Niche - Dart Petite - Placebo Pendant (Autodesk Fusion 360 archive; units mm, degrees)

design "Dart - Petite - Modular" references "Modular - Placebo - Bayonet Connector", "Modular - Placedo - Cord Set"
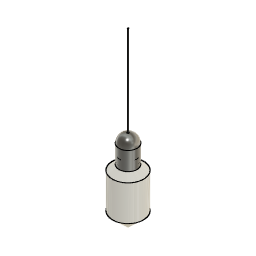
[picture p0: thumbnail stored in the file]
derived_base_feature "Derived Base Feature" bodies "Body1"
sketch "Sketch1" plane through (0, 0, 0) normal (0, 1, 0) x axis (1, 0, 0)
  line L1 (0, 127) -> (0, -444.5)
  line L2 (26.9875, 127) -> (26.9875, -444.5)
  line L3 (-26.9875, 127) -> (-26.9875, -444.5)
  point P4 (26.9875, -444.5)
  point P6 (-26.9875, -444.5)
  point P5 (26.9875, 127)
  point P7 (-26.9875, 127)
  vertical L1
  symmetric L1 P4 P6
  symmetric L1 P5 P7
  dimension "d1" = 26.9875
sketch "Sketch2" plane through (0, 0, 0) normal (0, 1, 0) x axis (1, 0, 0)
  line L1 (26.9371, -176.1141) -> (26.9371, -187.596)
  line L2 (-26.9875, -187.596) -> (-26.9875, -176.1141)
  line L3 (50.7748, -161.2156) -> (26.9371, -176.1141)
  line L4 (-26.9875, -176.1141) -> (-50.8252, -161.2156)
  line L5 (50.7748, -46.9156) -> (50.7748, -161.2156)
  line L6 (-50.8252, -161.2156) -> (-50.8252, -46.9156)
  line L7 (-0.0252, -0.0233) -> (50.7748, -46.9156)
  line L8 (-50.8252, -46.9156) -> (-0.0252, -0.0233)
  line L9 (26.9371, -187.596) -> (-26.9875, -187.596)
  line L10 (-49.5552, -47.4716) -> (0.8614, -0.9332)
  line L11 (-49.5552, -160.5117) -> (-49.5552, -47.4716)
  line L12 (-25.7175, -175.4102) -> (-49.5552, -160.5117)
  line L13 (-25.7175, -187.596) -> (-25.7175, -175.4102)
  line L14 (-0.0252, -0.0233) -> (-0.0252, -187.596)
  point P16 (-0.0252, -187.596)
  point P7 (-50.8252, -161.2156)
  point P9 (-50.8252, -46.9156)
  point P8 (50.7748, -161.2156)
  point P10 (50.7748, -46.9156)
  perpendicular L1 L9
  midpoint L9 P16
  perpendicular L9 L14
  dimension "d2" = -1.27
  dimension "d4" distance L5 L6 = 101.6
  dimension "d5" distance L5 L14 = 50.8
  dimension "d6" distance P7 P9 = 114.3
  dimension "d7" distance P8 P10 = 114.3
revolve "Revolve1" sketch "Sketch2" AlongAngle 360 bodies "Dart Petite Modular"
remove_body "RemoveBody1"
component_from_bodies "Body->Comp"
component_insert "Component Insert1"
component_insert "Component Insert2"
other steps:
base_feature "Base Feature" bodies "Dart Petite Modular"
create_component "CreateComponent1"
remove_body "RemoveBody2"
named bodies: "Body1", "Dart Petite Modular"

design "Modular - Placebo - Bayonet Connector"
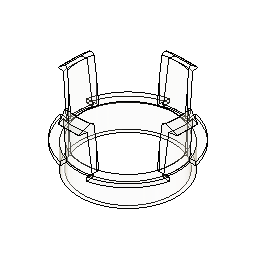
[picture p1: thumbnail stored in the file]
sketch "Sketch1" plane through (0, 0, 0) normal (0, 0, 1) x axis (1, 0, 0)
  circle C1 centre (0, 0) radius 23.241
  point P1 (0, 0)
  point P2 (0, 0)
  coincident P1 P2
  dimension "d1" diameter C1 = 46.482
extrude "Extrude1" new body sketch "Sketch1" along normal blind 11.176
sketch "Sketch2" plane through (0, 0, 11.176) normal (0, 0, 1) x axis (-1, 0, 0)
  line L1 (-23.2795, -6.35) -> (-26.1645, -6.35)
  line L2 (-23.2795, 6.35) -> (-26.1645, 6.35)
  line L3 (26.1645, -6.35) -> (23.2795, -6.35)
  line L4 (26.1645, 6.35) -> (23.2795, 6.35)
  line L5 (6.35, -23.2795) -> (6.35, -26.1645)
  line L6 (-6.35, -23.2795) -> (-6.35, -26.1645)
  line L7 (6.35, 26.1645) -> (6.35, 23.2795)
  line L8 (-6.35, 26.1645) -> (-6.35, 23.2795)
  line L9 (0, -24.13) -> (0, -26.924)
  line L10 (6.35, -23.2795) -> (6.35, -22.3567)
  line L11 (-6.35, -23.2795) -> (-6.35, -22.3567)
  line L12 (23.2795, -6.35) -> (22.3567, -6.35)
  line L13 (23.2795, 6.35) -> (22.3567, 6.35)
  line L14 (-23.2795, 6.35) -> (-22.3567, 6.35)
  line L15 (-23.2795, -6.35) -> (-22.3567, -6.35)
  line L16 (6.35, 22.3567) -> (6.35, 23.2795)
  line L17 (-6.35, 22.3567) -> (-6.35, 23.2795)
  circle C1 centre (0, 0) radius 23.241
  arc A1 centre (0, 0) radius 26.924 clockwise from (-6.35, -26.1645) to (-26.1645, -6.35)
  arc A2 centre (0, 0) radius 26.924 clockwise from (26.1645, -6.35) to (6.35, -26.1645)
  arc A3 centre (0, 0) radius 24.13 clockwise from (23.2795, 6.35) to (23.2795, -6.35)
  arc A4 centre (0, 0) radius 24.13 clockwise from (6.35, -23.2795) to (-6.35, -23.2795)
  arc A5 centre (0, 0) radius 26.924 clockwise from (6.35, 26.1645) to (26.1645, 6.35)
  arc A6 centre (0, 0) radius 26.924 clockwise from (-26.1645, 6.35) to (-6.35, 26.1645)
  arc A7 centre (0, 0) radius 24.13 clockwise from (-6.35, 23.2795) to (6.35, 23.2795)
  arc A8 centre (0, 0) radius 24.13 clockwise from (-23.2795, -6.35) to (-23.2795, 6.35)
  point P2 (0, 0)
  point P4 (0, 0)
  point P12 (-23.2795, -6.35)
  point P13 (-22.3567, -6.35)
  point P14 (-23.2795, 6.35)
  point P15 (-22.3567, 6.35)
  point P16 (22.3567, -6.35)
  point P18 (22.3567, 6.35)
  point P24 (6.35, 23.2795)
  point P28 (6.35, -22.3567)
  point P29 (-6.35, -22.3567)
  point P31 (-6.35, 26.1645)
  point P35 (0, -24.13)
  point P36 (6.35, 22.3567)
  point P37 (-6.35, 22.3567)
  coincident P2 P4
  vertical L9
  concentric A2 A3
  concentric A1 A2
  coincident P12 A3
  coincident C1 P13
  coincident P14 A3
  coincident C1 P15
  coincident C1 P16
  coincident C1 P18
  concentric A2 A5
  coincident P24 L5
  concentric A3 A7
  concentric A4 A7
  coincident C1 P28
  coincident C1 P29
  coincident P31 A5
  concentric A5 A6
  concentric A7 A8
  coincident A4 P35
  horizontal L12
  coincident C1 P36
  parallel L7 L16
  coincident C1 P37
  parallel L8 L17
  dimension "d4" diameter A2 = 53.848
extrude "Extrude2" add sketch "Sketch2" profile of C1 A8 L10 L11 L12 L13 L14 L15 L16 L17 along normal blind 0.762
extrude "Extrude3" add sketch "Sketch2" profile of C1 A6 L7 L8 L4 L3 L10 L11 L12 L13 L14 L15 L16 L17 along normal blind 1.7018
extrude "Extrude4" add sketch "Sketch2" profile of C1 along normal blind 1.7018
work_plane "WorkPlane1" AlongDistance 33.8963
sketch "Sketch3" plane through (0, 0, 33.8963) normal (0, 0, 1) x axis (1, 0, 0)
  line L1 (0, 20.3925) -> (0, 27.5045)
  line L2 (-6.604, 20.3925) -> (-6.604, 27.5045)
  line L3 (6.604, 20.3925) -> (6.604, 27.5045)
  circle C1 centre (0, 0) radius 23.7363
  circle C2 centre (0, 0) radius 27.305
  arc A1 centre (0.0021, 0.2001) radius 23.9364 clockwise from (-6.604, 23.2068) to (6.604, 23.208)
  arc A2 centre (0.0021, 0.2001) radius 21.3964 clockwise from (-6.604, 20.5511) to (6.604, 20.5525)
  point P1 (0, 0)
  point P2 (0, 0)
  point P6 (-6.604, 27.5045)
  point P8 (6.604, 27.5045)
  point P7 (-6.604, 20.3925)
  point P9 (6.604, 20.3925)
  point P11 (-6.604, 23.2068)
  point P12 (6.604, 23.208)
  point P14 (-6.604, 20.5511)
  point P15 (6.604, 20.5525)
  coincident P1 P2
  concentric C1 C2
  vertical L1
  symmetric L1 P6 P8
  symmetric L1 P7 P9
  tangent C1 A1
  coincident L2 P11
  coincident L3 P12
  concentric A1 A2
  coincident L2 P14
  coincident L3 P15
  dimension "d14" diameter C1 = 47.4726
  dimension "d15" diameter C2 = 54.61
  dimension "d16" = 6.604
extrude "Extrude5" new body sketch "Sketch3" profile of C1 L1 L2 L3 A1 A2 against normal blind 21.59
sketch "Sketch4" plane through (0, 0, 33.8963) normal (0, 0, 1) x axis (-1, 0, 0)
  line L1 (6.604, -20.5511) -> (6.604, -23.2068)
  line L2 (-6.604, -23.208) -> (-6.604, -20.5525)
  line L3 (-5.08, -26.67) -> (-6.604, -20.5525)
  line L4 (5.08, -26.67) -> (-5.08, -26.67)
  line L5 (6.604, -20.5511) -> (5.08, -26.67)
  arc A1 centre (-0.0021, -0.2001) radius 23.9364 clockwise from (6.604, -23.2068) to (-6.604, -23.208)
  arc A2 centre (-0.0021, -0.2001) radius 21.3964 clockwise from (6.604, -20.5511) to (-6.604, -20.5525)
  point P6 (-6.604, -20.5525)
  point P7 (-6.604, -20.5525)
  point P5 (6.604, -20.5511)
  point P10 (6.604, -20.5511)
  coincident P6 P7
  perpendicular L2 L4
  coincident P5 P10
extrude "Extrude6" add sketch "Sketch4" profile of A1 A2 L3 L4 L5 against normal blind 3.175
move "Move1"
sketch "Sketch5" plane through (0, 3.4565, 35.8974) normal (0, 0.0958, 0.9954) x axis (-1, 0, 0)
  line L1 (6.604, -19.277) -> (6.604, -21.9327)
  line L2 (-6.604, -21.9339) -> (-6.604, -19.2784)
  line L3 (-5.08, -25.3959) -> (-5.8947, -22.1257)
  line L4 (5.08, -25.3959) -> (-5.08, -25.3959)
  line L5 (5.8948, -22.1246) -> (5.08, -25.3959)
  line L6 (-8.1218, -17.3223) -> (-6.0831, -25.506)
  line L7 (-0.004, -17.3223) -> (-0.0002, -17.3223)
  line L8 (-8.1218, -17.3223) -> (-6.8295, -17.3223)
  line L9 (0, -25.3959) -> (0.0001, -20.3223)
  line L10 (-6.8295, -17.3223) -> (-4.7917, -25.5025)
  line L11 (8.1222, -17.3227) -> (6.0831, -25.5062)
  line L12 (8.1222, -17.3227) -> (6.8299, -17.3226)
  line L13 (-4.7917, -25.5025) -> (-6.1096, -25.506)
  line L14 (4.7917, -25.5027) -> (6.0831, -25.5062)
  line L15 (6.8299, -17.3226) -> (4.7917, -25.5027)
  arc A1 centre (-0.0021, 1.074) radius 23.9364 clockwise from (6.604, -21.9327) to (5.8948, -22.1246)
  arc A2 centre (-0.0021, 1.074) radius 21.3964 clockwise from (6.604, -19.277) to (-6.604, -19.2784)
  arc A3 centre (-0.0021, 1.074) radius 23.9364 clockwise from (-5.8947, -22.1257) to (-6.604, -21.9339)
  arc A4 centre (-0.0021, 1.074) radius 18.3964 clockwise from (5.6778, -16.4236) to (-5.6783, -16.4247)
  point P14 (-0.0002, -17.3223)
  point P15 (-8.1218, -17.3223)
  point P16 (-0.004, -17.3223)
  point P17 (0.0001, -20.3223)
  point P18 (0, -25.3959)
  point P20 (8.1222, -17.3227)
  point P19 (-6.8295, -17.3223)
  point P21 (6.8299, -17.3226)
  point P23 (-6.0831, -25.506)
  point P26 (6.8299, -17.3226)
  point P24 (-4.7917, -25.5025)
  point P25 (4.7917, -25.5027)
  midpoint A4 P14
  horizontal L7
  coincident P15 L7
  coincident A4 P16
  collinear L7 L8
  midpoint A2 P17
  midpoint L4 P18
  symmetric P15 L9 P20
  symmetric L9 P19 P21
  coincident L13 P23
  symmetric L9 P19 P26
  symmetric L9 P24 P25
  dimension "d22" = -3
extrude "Extrude7" cut sketch "Sketch5" profile of A1 L1 A2 L2 A3 L3 L4 L5 L8 L6 L10 L11 L12 L13 L14 L15 against normal blind 25.146 taper -1.45
remove_body "RemoveBody1"
remove_body "RemoveBody2"
chamfer "Chamfer1" sketch "Sketch4" distance 4.572 distance 3.048
circular_pattern "C-Pattern1" TotalAngle 360
extrude "Extrude8" add sketch "Sketch4" along a picked direction blind 0.508
extrude "Extrude9" add of existing geometry blind 0.508
extrude "Extrude10" add of existing geometry blind 0.508
extrude "Extrude11" add of existing geometry blind 0.508
hole "Hole1" sketch "Sketch4" HoleDepth 38.1 HoleDiameter 42.926 TipAngle 118
fillet "Fillet1" sketch "Sketch4" radius 1.27

design "Modular - Placedo - Cord Set"
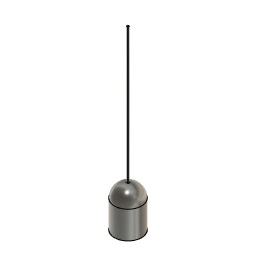
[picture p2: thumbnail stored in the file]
sketch "Sketch1" plane through (0, 0, 0) normal (0, 1, 0) x axis (1, 0, 0)
  line L1 (0, -88.9) -> (0, 0)
  line L2 (-29.5402, -88.9) -> (-29.5402, 0)
  line L3 (29.5402, -88.9) -> (29.5402, 0)
  line L4 (29.5402, 8.5598) -> (29.5402, -59.3598)
  line L5 (-29.5402, -59.3598) -> (-29.5402, 8.5598)
  line L6 (0, 38.1) -> (0, -88.9)
  line L7 (29.5402, 0) -> (-29.5402, 0)
  arc A1 centre (0, 8.5598) radius 29.5402 clockwise from (-29.5402, 8.5598) to (29.5402, 8.5598)
  arc A2 centre (0, -59.3598) radius 29.5402 clockwise from (29.5402, -59.3598) to (-29.5402, -59.3598)
  point P1 (0, 0)
  point P2 (0, 0)
  point P4 (-29.5402, 0)
  point P6 (29.5402, 0)
  point P5 (-29.5402, -88.9)
  point P7 (29.5402, -88.9)
  point P3 (0, -88.9)
  point P14 (0, 38.1)
  coincident P1 P2
  vertical L1
  symmetric L1 P4 P6
  symmetric L1 P5 P7
  tangent L4 A1
  tangent A1 L5
  parallel L4 L5
  tangent L5 A2
  tangent L4 A2
  midpoint P3 A2
  midpoint A1 P14
  parallel L1 L6
  dimension "d1" = 29.5402
revolve "Revolve1" sketch "Sketch1" AlongAngle 360
shell "Shell1" innerThickness 1.524
sketch "Sketch2" plane through (0, 0, 0) normal (0, 0, 1) x axis (1, 0, 0)
  circle C1 centre (0, 0) radius 2.8575
  point P1 (0, 0)
  point P2 (0, 0)
  coincident P1 P2
  dimension "d4" diameter C1 = 5.715
extrude "Extrude1" cut sketch "Sketch2" along normal blind 101.6
sketch "Sketch3" plane through (0, 0, 0) normal (0, 0, 1) x axis (1, 0, 0)
  circle C1 centre (0, 0) radius 2.286
  point P1 (0, 0)
  point P2 (0, 0)
  coincident P1 P2
  dimension "d7" diameter C1 = 4.572
extrude "Extrude2" new body sketch "Sketch3" along normal blind 304.8
move "Move1"
sketch "Sketch4" plane through (0, 0, 0) normal (0, 0, 1) x axis (1, 0, 0)
  circle C1 centre (0, 0) radius 18.796
  point P1 (0, 0)
  point P2 (0, 0)
  coincident P1 P2
  dimension "d10" diameter C1 = 37.592
extrude "Extrude3" new body sketch "Sketch4" along normal blind 31.75
move "Move2"
offset_faces "OffsetFaces1" distance 38.1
